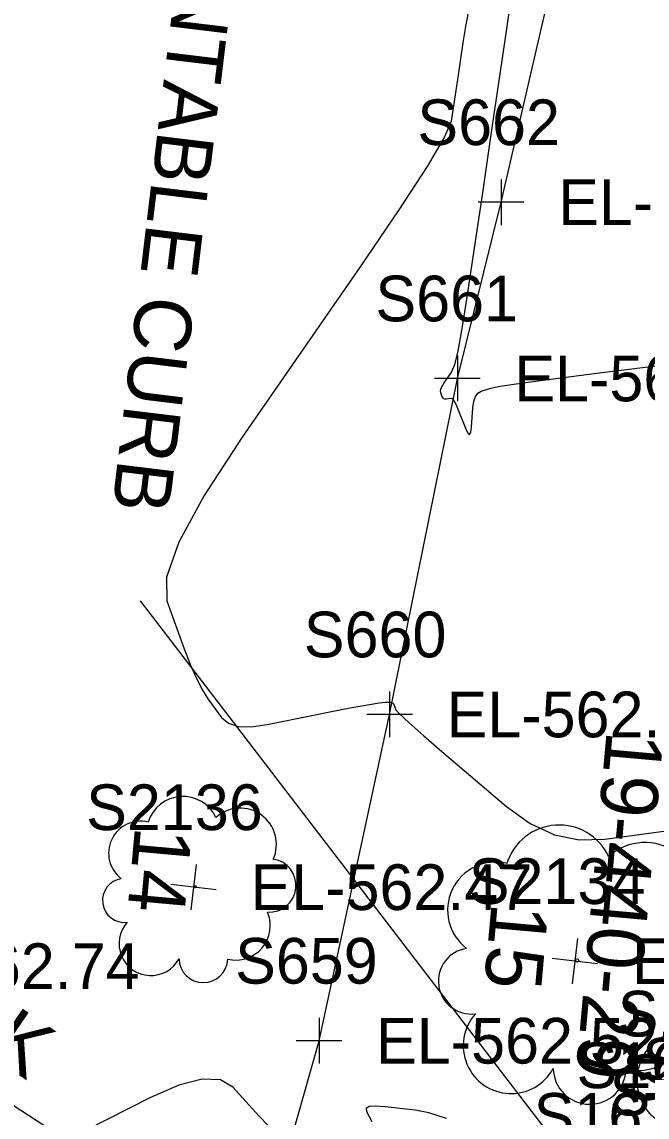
# Model space of a CAD drawing. Extents: x 1724534 to 1727318, y 657156 to 660047.
# Drawn here: x 1725337.1 to 1725391.9, y 658704.6 to 658800.5 of the extents above; entities that cross this region are included whole.
import ezdxf

# ---------------------------------------------------------------- set-up
doc = ezdxf.new("R2010")
doc.units = 0
for name, color, linetype in [('SURVEY - CONTOURS - Intermediate with optional Text', 7, 'Continuous'), ('SURVEY - CONTROL with Text', 7, 'Continuous'), ('SURVEY - NON-TRANSPORTATION - Features', 7, 'Continuous'), ('SURVEY - NON-TRANSPORTATION - Features - Points - Elevations', 7, 'Continuous'), ('SURVEY - NON-TRANSPORTATION - Features - Points - Locators', 7, 'Continuous'), ('SURVEY - NON-TRANSPORTATION - Features - Points - Numbers', 7, 'Continuous'), ('SURVEY - NON-TRANSPORTATION - Features Text', 7, 'Continuous'), ('SURVEY - TRANSPORTATION - Features - Points - Numbers', 7, 'Continuous'), ('SURVEY - TRANSPORTATION - Features Text', 7, 'Continuous'), ('SURVEY - TRANSPORTATION - Roads - Points - Numbers', 7, 'Continuous'), ('SURVEY - VEGETATION - Features - Points - Elevations', 7, 'Continuous'), ('SURVEY - VEGETATION - Features - Points - Locators', 7, 'Continuous'), ('SURVEY - VEGETATION - Features - Points - Numbers', 7, 'Continuous'), ('SURVEY - VEGETATION - Features with Text', 7, 'Continuous')]:
    doc.layers.add(name, color=color, linetype=linetype)

msp = doc.modelspace()

# ---------------------------------------------------------------- linework, layer by layer
at = {"layer": 'SURVEY - CONTOURS - Intermediate with optional Text'}
for points in [[(1725376.427, 658802.395), (1725376.005, 658800.133), (1725375.794, 658798.894), (1725375.293, 658795.475), (1725374.752, 658791.842), (1725374.165, 658790.455), (1725372.638, 658787.866), (1725370.17, 658784.074), (1725366.762, 658779.08), (1725356.421, 658764.156), (1725353.1, 658759.063), (1725350.892, 658754.977), (1725349.798, 658751.897), (1725349.817, 658749.824), (1725351.354, 658745.639), (1725351.915, 658744.188), (1725352.446, 658742.975), (1725352.947, 658742), (1725353.418, 658741.262), (1725354.633, 658739.612), (1725355.223, 658739.11), (1725356.082, 658738.839), (1725357.211, 658738.801), (1725358.609, 658738.994), (1725362.695, 658739.818), (1725364.108, 658740.102), (1725365.281, 658740.332), (1725366.214, 658740.511), (1725366.908, 658740.637), (1725368.44, 658740.904), (1725368.951, 658740.969), (1725369.335, 658740.967), (1725369.593, 658740.896), (1725369.724, 658740.758), (1725369.905, 658740.297), (1725370.22, 658739.927), (1725371.029, 658739.165), (1725372.334, 658738.01), (1725374.132, 658736.462), (1725379.587, 658731.811), (1725381.66, 658730.324), (1725383.785, 658729.352), (1725385.964, 658728.894), (1725388.196, 658728.951), (1725394.218, 658729.789)], [(1725379.925, 658802.159), (1725379.55, 658799.701), (1725378.229, 658790.671), (1725377.474, 658785.561), (1725376.029, 658775.857), (1725375.654, 658773.493), (1725375.321, 658771.71), (1725375.029, 658770.508), (1725374.778, 658769.886), (1725374.165, 658769.002), (1725373.97, 658768.695), (1725373.844, 658768.439), (1725373.788, 658768.234), (1725373.801, 658768.079), (1725373.927, 658767.734), (1725373.986, 658767.624), (1725374.068, 658767.552), (1725374.172, 658767.518), (1725374.299, 658767.523), (1725374.669, 658767.587), (1725374.818, 658767.536), (1725374.989, 658767.335), (1725375.182, 658766.984), (1725375.397, 658766.483), (1725376, 658764.946), (1725376.203, 658764.521), (1725376.36, 658764.396), (1725376.471, 658764.573), (1725376.536, 658765.051), (1725376.647, 658766.727), (1725376.723, 658767.29), (1725376.869, 658767.721), (1725377.083, 658768.021), (1725377.366, 658768.189), (1725378.213, 658768.462), (1725379.033, 658768.619), (1725380.857, 658768.888), (1725383.684, 658769.266), (1725387.516, 658769.755), (1725399.073, 658771.207)], [(1725358.695, 658703.894), (1725357.918, 658704.714), (1725355.62, 658707.244), (1725354.519, 658707.897), (1725352.939, 658707.958), (1725350.88, 658707.429), (1725348.342, 658706.308), (1725340.937, 658702.532)], [(1725374.336, 658704.51), (1725372.774, 658704.998), (1725371.593, 658705.235), (1725368.953, 658705.533), (1725368.109, 658705.59), (1725367.556, 658705.539), (1725367.294, 658705.379), (1725367.323, 658705.111), (1725367.79, 658704.25)]]:
    msp.add_lwpolyline(points, dxfattribs=at)
at = {"layer": 'SURVEY - CONTROL with Text'}
msp.add_circle((1725395.383, 658707.853), 4.35, dxfattribs=at)
at = {"layer": 'SURVEY - NON-TRANSPORTATION - Features'}
for points in [[(1725357.884, 658691.6), (1725317.495, 658717.924), (1725277.546, 658743.26), (1725284.233, 658843.735), (1725290.685, 658948.071), (1725297.823, 659048.449), (1725304.359, 659146.85), (1725311.219, 659244.818), (1725312.69, 659284.205)], [(1725357.678, 658691.928), (1725363.165, 658711.31), (1725369.342, 658739.883), (1725375.283, 658769.307), (1725379.116, 658784.738), (1725384.76, 658809.108), (1725393.359, 658848.496), (1725405.647, 658900.795), (1725418.141, 658956.869), (1725428.713, 659003.816), (1725429.417, 659007.151)]]:
    msp.add_lwpolyline(points, dxfattribs=at)
at = {"layer": 'SURVEY - NON-TRANSPORTATION - Features - Points - Locators'}
for p, q in [((1725379.116, 658786.738), (1725379.116, 658782.738)), ((1725381.116, 658784.738), (1725377.116, 658784.738)), ((1725375.283, 658771.307), (1725375.283, 658767.307)), ((1725377.283, 658769.307), (1725373.283, 658769.307)), ((1725369.342, 658741.883), (1725369.342, 658737.883)), ((1725371.342, 658739.883), (1725367.342, 658739.883)), ((1725363.165, 658713.31), (1725363.165, 658709.31)), ((1725365.165, 658711.31), (1725361.165, 658711.31))]:
    msp.add_line(p, q, dxfattribs=at)
at = {"layer": 'SURVEY - TRANSPORTATION - Features Text'}
msp.add_line((1725403.623, 658676.693), (1725347.514, 658749.838), dxfattribs=at)
at = {"layer": 'SURVEY - VEGETATION - Features - Points - Locators'}
for p, q in [((1725352.397, 658726.743), (1725351.925, 658722.771)), ((1725354.147, 658724.521), (1725350.175, 658724.993)), ((1725385.811, 658720.27), (1725385.339, 658716.298)), ((1725387.561, 658718.048), (1725383.589, 658718.52))]:
    msp.add_line(p, q, dxfattribs=at)
at = {"layer": 'SURVEY - VEGETATION - Features with Text'}
for centre, radius in [((1725352.297, 658724.792), 0.0978), ((1725385.779, 658718.337), 0.147)]:
    msp.add_circle(centre, radius, dxfattribs=at)
for centre, radius, start, end in [((1725351.246, 658729.507), 3.194, 25.19624, 162.72047), ((1725356.258, 658728.505), 3.174, 336.09207, 131.93055), ((1725347.532, 658727.733), 2.804, 76.1435, 232.93242), ((1725384.203, 658725.408), 4.792, 25.19624, 162.72047), ((1725391.72, 658723.907), 4.76, 336.09207, 131.93055), ((1725358.807, 658724.905), 2.34, 266.34497, 81.34525), ((1725378.631, 658722.748), 4.205, 76.1435, 232.93242), ((1725346.118, 658723.591), 1.924, 98.25965, 277.0053), ((1725355.882, 658721.39), 3.016, 256.18606, 23.03173), ((1725348.441, 658719.82), 2.798, 138.28034, 331.70003), ((1725376.511, 658716.535), 2.887, 98.25965, 277.0053), ((1725353.033, 658718.527), 2.129, 180.89901, 358.21815), ((1725391.156, 658713.233), 4.525, 256.18606, 23.03173), ((1725379.995, 658710.878), 4.196, 138.28034, 331.70003), ((1725386.883, 658708.938), 3.194, 180.89901, 358.21815)]:
    msp.add_arc(centre, radius, start, end, dxfattribs=at)

# ---------------------------------------------------------------- texts
at = {"layer": 'SURVEY - CONTROL with Text'}
msp.add_text('19-440-29', height=5, rotation=264.87201, dxfattribs=at).set_placement((1725388.373, 658738.52))
at = {"layer": 'SURVEY - NON-TRANSPORTATION - Features - Points - Elevations'}
for s, p in [('EL-560.52', (1725384.116, 658782.738)), ('EL-560.94', (1725380.283, 658767.307)), ('EL-562.05', (1725374.342, 658737.883)), ('EL-562.74', (1725322.762, 658715.841)), ('EL-562.52', (1725368.165, 658709.31))]:
    msp.add_text(s, height=4, dxfattribs=at).set_placement(p)
at = {"layer": 'SURVEY - NON-TRANSPORTATION - Features - Points - Numbers'}
for s, p in [('S662', (1725371.78, 658789.738)), ('S661', (1725368.105, 658774.307)), ('S660', (1725361.833, 658744.883)), ('S659', (1725355.813, 658716.31))]:
    msp.add_text(s, height=4, dxfattribs=at).set_placement(p)
at = {"layer": 'SURVEY - NON-TRANSPORTATION - Features Text'}
msp.add_text('CHAINLINK', height=5, rotation=325.72105, dxfattribs=at).set_placement((1725308.148, 658727.875))
at = {"layer": 'SURVEY - TRANSPORTATION - Features - Points - Numbers'}
for s, p in [('S1669', (1725389.334, 658711.683)), ('S1670', (1725385.731, 658707.159)), ('S1671', (1725381.971, 658702.729))]:
    msp.add_text(s, height=4, dxfattribs=at).set_placement(p)
at = {"layer": 'SURVEY - TRANSPORTATION - Features Text'}
msp.add_text('MOUNTABLE CURB', height=5, rotation=263.09355, dxfattribs=at).set_placement((1725352.522, 658819.863))
at = {"layer": 'SURVEY - TRANSPORTATION - Roads - Points - Numbers'}
for s, p in [('S1335', (1725391.477, 658707.562)), ('S1334', (1725390.088, 658706.124)), ('S1333', (1725388.619, 658704.768))]:
    msp.add_text(s, height=4, dxfattribs=at).set_placement(p)
at = {"layer": 'SURVEY - VEGETATION - Features - Points - Elevations'}
for s, p in [('EL-562.47', (1725357.161, 658722.757)), ('EL-562.58', (1725390.575, 658716.284))]:
    msp.add_text(s, height=4, dxfattribs=at).set_placement(p)
at = {"layer": 'SURVEY - VEGETATION - Features - Points - Numbers'}
for s, p in [('S2136', (1725342.763, 658729.757)), ('S2134', (1725376.287, 658723.284))]:
    msp.add_text(s, height=4, dxfattribs=at).set_placement(p)
at = {"layer": 'SURVEY - VEGETATION - Features with Text'}
for s, p in [('14', (1725347.053, 658730.159)), ('15', (1725378.29, 658723.466))]:
    msp.add_text(s, height=5, rotation=264.87201, dxfattribs=at).set_placement(p)

doc.saveas('drawing.dxf')
